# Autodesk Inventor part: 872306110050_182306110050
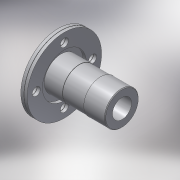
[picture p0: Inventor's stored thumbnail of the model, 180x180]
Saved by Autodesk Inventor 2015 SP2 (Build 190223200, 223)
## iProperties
Created: 2017-02
Part Number: 872306110050_182306110050
Material: PVC-Piping
Description: PLASSON FLANGE ADAPTOR WITH METAL FLANGE 110-5"
Document SubType Name: Modeling
Designer: KIM
Mass: 92.6774 g
Surface Area: 199.44 cm^2
Volume: 66.1981 cm^3
Density: 1.4 g/cm^3
Appearance: Smooth - White
Author: Кирилл
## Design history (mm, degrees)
derived "872306.ipt"
feature "Solid1::872306.ipt"
tag "TaggingFeature1"
body "Solid1"
other parameters: "d73" = 21.4, "d74" = 90 deg, "d75" = 0.3, "d77" = 18, "d78" = 105, "d80" = 0, "d82" = 360 deg, "d94" = 125, "d96" = 0.3, "d99" = 360 deg, "d103" = 214, "d104" = 2.2, "d107" = 143, "d108" = 5.35, "d116" = 107.8, "d117" = 71.33333, "d118" = 71.33333, "d120" = 16.5, "H_" = 214, "S_" = 18, "DN_" = 125
